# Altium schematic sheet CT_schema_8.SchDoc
size 254 x 194 mm
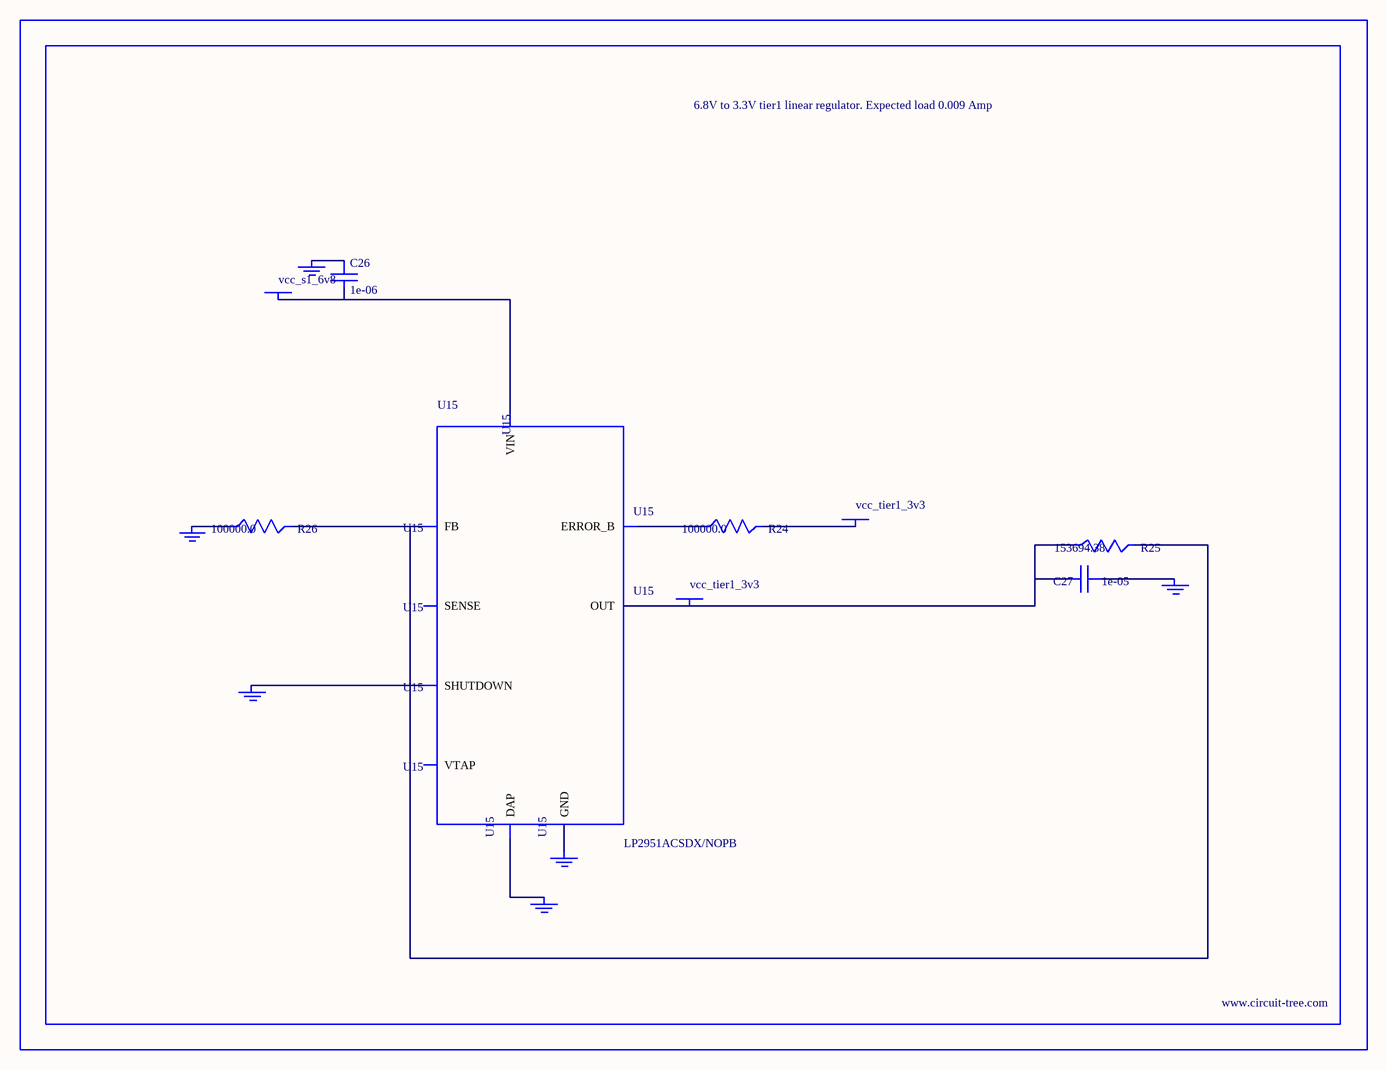
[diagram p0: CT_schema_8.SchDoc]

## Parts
BORDER7  (no value)
C26  1e-06  [C0603]
C27  1e-05  [C1210]
GND_INSTANCE_7_0  (no value)
GND_INSTANCE_7_1  (no value)
GND_INSTANCE_7_2  (no value)
GND_INSTANCE_7_3  (no value)
GND_INSTANCE_7_4  (no value)
GND_INSTANCE_7_5  (no value)
POWER_INSTANCE_7_0  vcc_tier1_3v3
POWER_INSTANCE_7_1  vcc_s1_6v8
POWER_INSTANCE_7_2  vcc_tier1_3v3
R24  100000.0  [R0603]
R25  153694.38  [R0603]
R26  100000.0  [R0603]
U15  LP2951ACSDX/NOPB  [WSON-8]

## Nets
NetC26_1: C26.1 GND_INSTANCE_7_3.0(GND)
NetC26_2: C26.2 POWER_INSTANCE_7_1.0(PWR) U15.8(VIN)
NetC27_1: C27.1 GND_INSTANCE_7_0.0(GND)
NetC27_2: C27.2 POWER_INSTANCE_7_2.0(PWR) R25.1 U15.1(OUT)
NetGND_INSTANCE_7_1_0: GND_INSTANCE_7_1.0(GND) U15.3(SHUTDOWN)
NetGND_INSTANCE_7_2_0: GND_INSTANCE_7_2.0(GND) R26.1
NetGND_INSTANCE_7_4_0: GND_INSTANCE_7_4.0(GND) U15.PAD(DAP)
NetGND_INSTANCE_7_5_0: GND_INSTANCE_7_5.0(GND) U15.4(GND)
NetPOWER_INSTANCE_7_0_0: POWER_INSTANCE_7_0.0(PWR) R24.2
NetR24_1: R24.1 U15.5(ERROR_B)
NetR25_2: R25.2 R26.2 U15.7(FB)

Not connected (* = marked no-connect by the designer): U15 2(SENSE) 6(VTAP)

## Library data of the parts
BORDER7 = BORDER_PAGE7
C26 = C0603C105K3RACTU
C27 = GRM32DR61E106MA12L
GND_INSTANCE_7_0-GND_INSTANCE_7_5 = GND
POWER_INSTANCE_7_0-POWER_INSTANCE_7_2 = PWR
R24 R26 = RC0603JR-07100KL
R25 = R25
